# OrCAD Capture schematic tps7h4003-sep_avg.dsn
size Custom; title: TPS7H4003-SEP Radiation-Tolerant 3-V to 7-V Input; rev: *; note: Datasheet: SLVSG41    EVM User Guide: SLVUC73; note: 18-A Synchronous Buck Converter in Space Enhanced Plastic
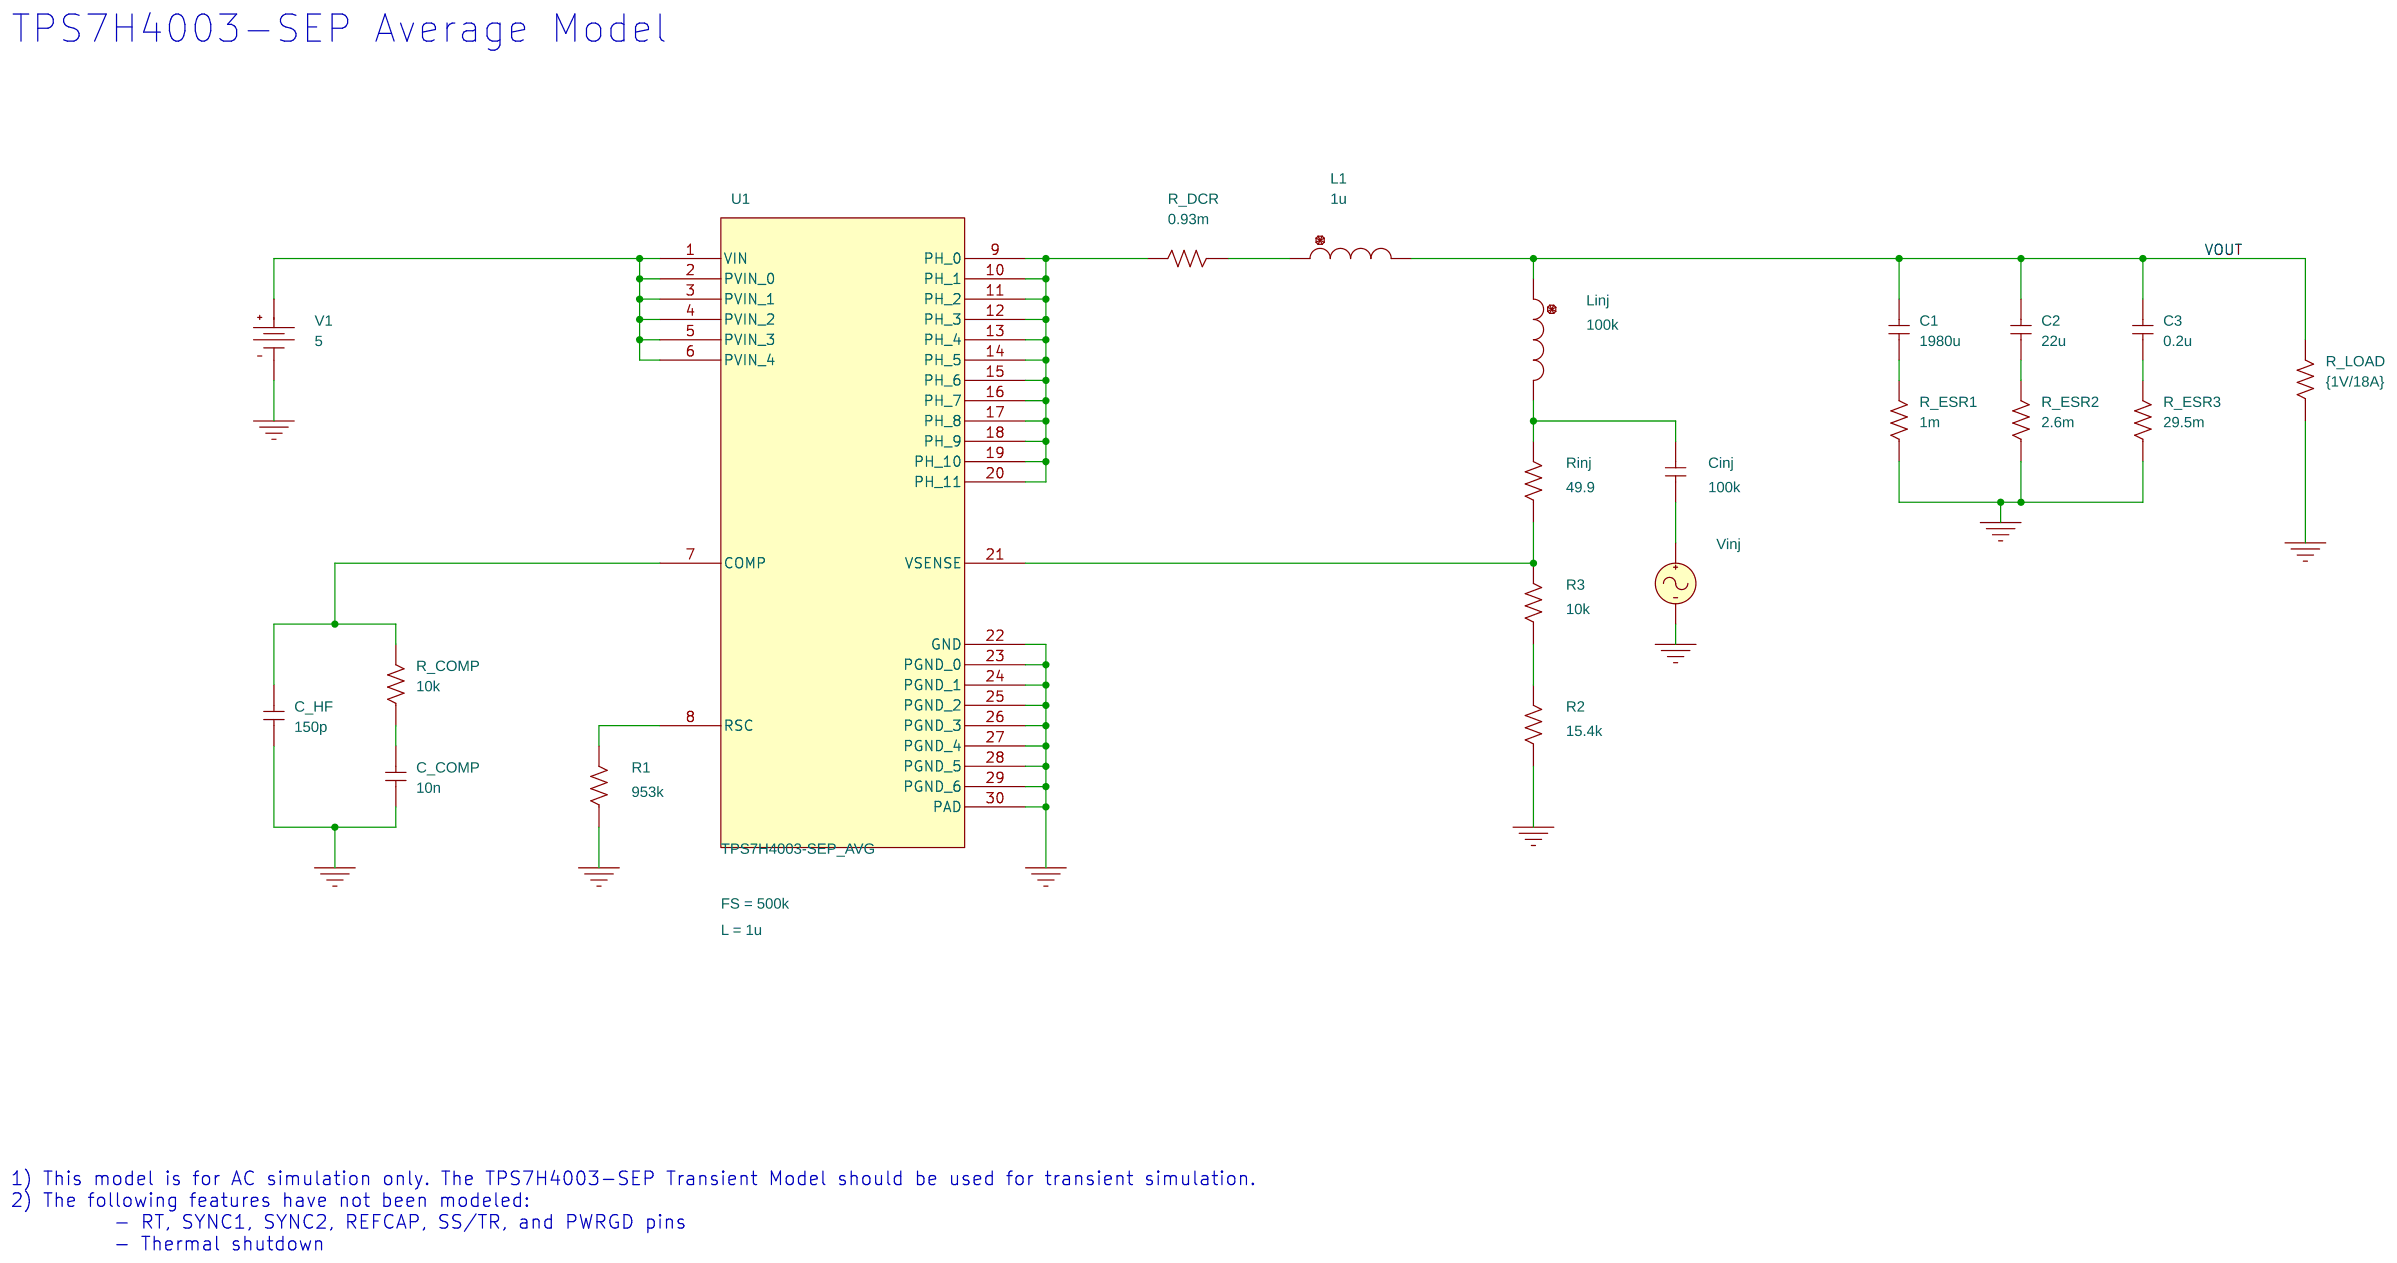
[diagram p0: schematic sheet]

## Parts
C1  1980u  [cap196]
C2  22u  [cap196]
C3  0.2u  [cap196]
C_COMP  10n  [cap196]
C_HF  150p  [cap196]
Cinj  100k  [cap196]
L1  1u  [DISC350x175LS200x100034]
Linj  100k  [DISC350x175LS200x100034]
R1  953k  [AXRC05]
R2  15.4k  [AXRC05]
R3  10k  [AXRC05]
R_COMP  10k  [AXRC05]
R_DCR  0.93m  [AXRC05]
R_ESR1  1m  [AXRC05]
R_ESR2  2.6m  [AXRC05]
R_ESR3  29.5m  [AXRC05]
R_LOAD  {1V/18A}  [AXRC05]
Rinj  49.9  [AXRC05]
U1  TPS7H4003-SEP_AVG
V1  VDC
Vinj  VAC

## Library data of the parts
C1-C3 C_COMP C_HF Cinj = C
L1 Linj = L
R1-R3 R_COMP R_DCR R_ESR1-R_ESR3 R_LOAD Rinj = R
U1 = TPS7H4003-SEP_AVG_0: FS: 500k; L: 1u; PSpiceTemplate: X^@REFDES  %VIN %PVIN_0 %PVIN_1 %PVIN_2 %PVIN_3 %PVIN_4 %COMP %RSC %PH_0 %PH_1 %PH_2 %PH_3 %PH_4 %PH_5 %PH_6 %PH_7 %PH_8 %PH_9 %PH_10 %PH_11 %VSENSE %GND %PGND_0 %PGND_1 %PGND_2 %PGND_3 %PGND_4 %PGND_5 %PGND_6 %PAD @MODEL PARAMS: ?FS|FS=@FS||FS=500k| ?L|L=@L||L=0.9u|
V1 = VDC: DC: 5
Vinj = VAC

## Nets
0: C_COMP.1 C_HF.1 R1.1 R2.1 R_ESR1.1 R_ESR2.1 R_ESR3.1 R_LOAD.1 U1.22(GND) U1.23(PGND_0) U1.24(PGND_1) U1.25(PGND_2) U1.26(PGND_3) U1.27(PGND_4) U1.28(PGND_5) U1.29(PGND_6) U1.30(PAD) V1.1(-) Vinj.2(-)
VOUT: C1.2 C2.2 C3.2 L1.2 Linj.1 R_LOAD.2
N16770976: C_COMP.2 R_COMP.1
N16770984: C_HF.2 R_COMP.2 U1.7(COMP)
N16771181: R1.2 U1.8(RSC)
N16771534: U1.1(VIN) U1.2(PVIN_0) U1.3(PVIN_1) U1.4(PVIN_2) U1.5(PVIN_3) U1.6(PVIN_4) V1.0(+)
N16771882: R_DCR.2 U1.9(PH_0) U1.10(PH_1) U1.11(PH_2) U1.12(PH_3) U1.13(PH_4) U1.14(PH_5) U1.15(PH_6) U1.16(PH_7) U1.17(PH_8) U1.18(PH_9) U1.19(PH_10) U1.20(PH_11)
N16772748: L1.1 R_DCR.1
N16773114: R3.2 Rinj.1 U1.21(VSENSE)
N16773116: R2.2 R3.1
N16773665: C1.1 R_ESR1.2
N16774131: C2.1 R_ESR2.2
N16774243: C3.1 R_ESR3.2
N16775894: Cinj.1 Vinj.1(+)
N16776362: Cinj.2 Linj.2 Rinj.2

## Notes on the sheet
- TPS7H4003-SEP Average Model
- 1) This model is for AC simulation only. The TPS7H4003-SEP Transient Model should be used for transient simulation.
  2) The following features have not been modeled:
            - RT, SYNC1, SYNC2, REFCAP, SS/TR, and PWRGD pins
            - Thermal shutdown
